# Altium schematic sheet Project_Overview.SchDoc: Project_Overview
size A4; Date: Not used; ApprovedBy: Not used; CheckedBy: Not used; Author: Not used; CompanyName: STMicroelectronics; DrawnBy: Not used; Engineer: Not used; Organization: Not used; Address1: Not used; Address2: Not used; Address3: Not used; Address4: Not used; DocumentNumber: 1; Revision: Not used; SheetNumber: 1; SheetTotal: 15
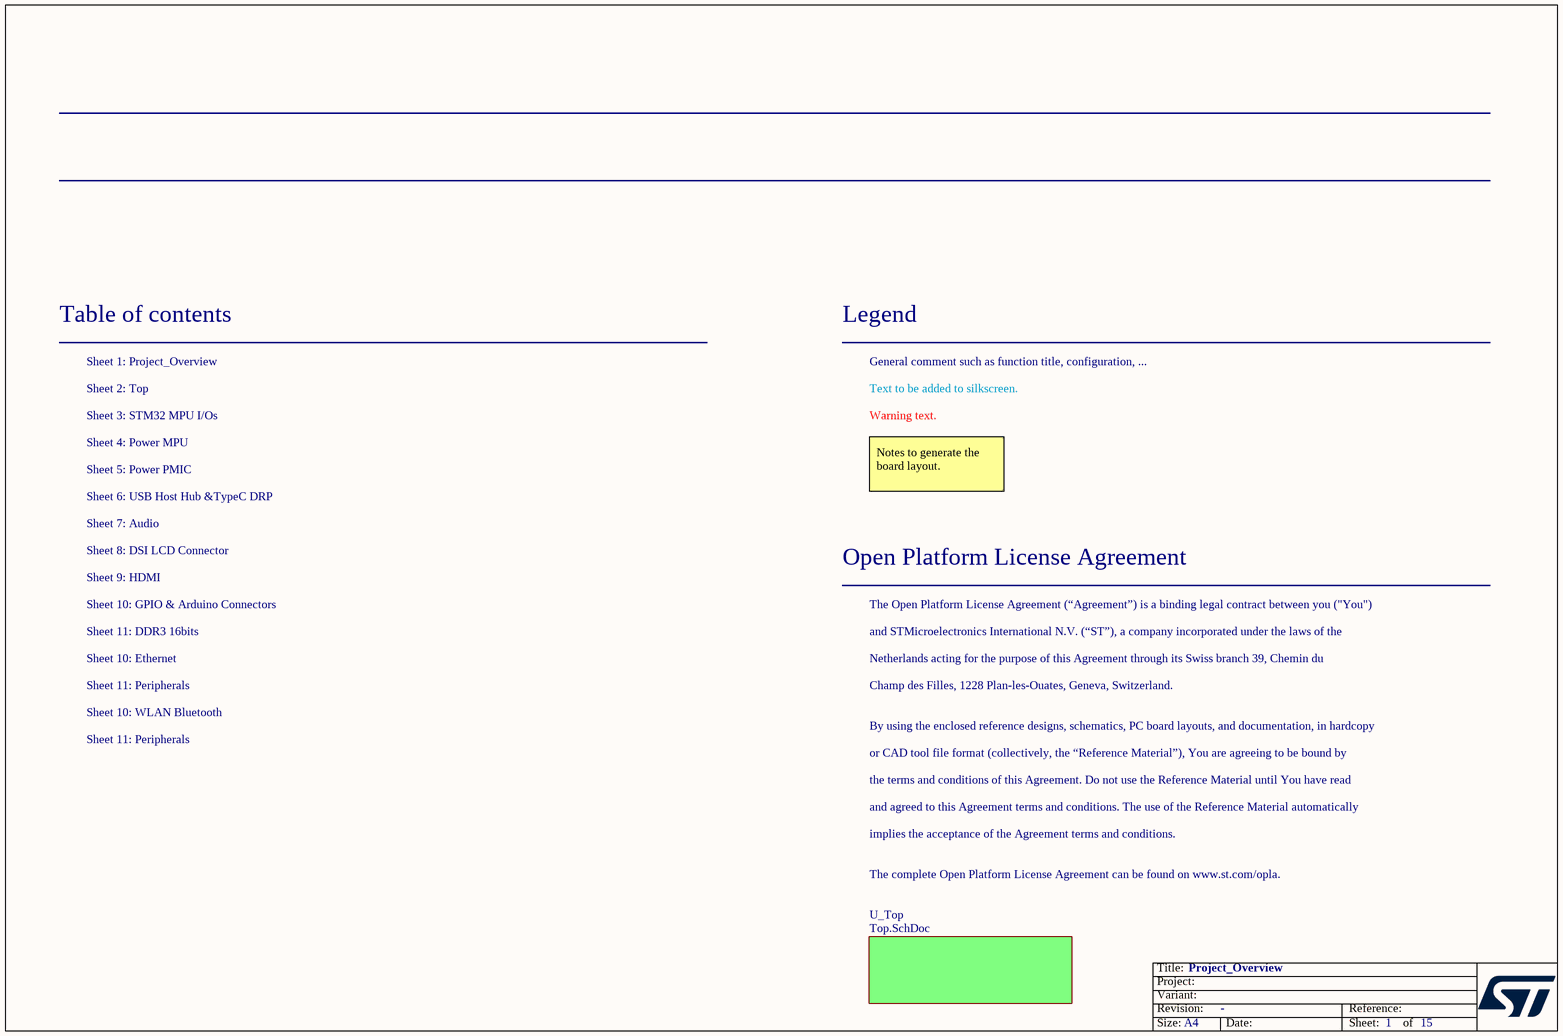
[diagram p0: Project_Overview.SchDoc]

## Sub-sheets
U_Top = Top.SchDoc: no entries

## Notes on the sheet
- Table of contents
- Sheet 1: Project_Overview
- Legend
- General comment such as function title, configuration, ...
- Sheet 2: Top
- Sheet 3: STM32 MPU I/Os
- Sheet 4: Power MPU
- Text to be added to silkscreen.
- Warning text.
- Sheet 6: USB Host Hub &TypeC DRP
- Sheet 5: Power PMIC
- Notes to generate the board layout.
- Sheet 7: Audio
- Sheet 9: HDMI
- Sheet 8: DSI LCD Connector
- Open Platform License Agreement
- Sheet 10: GPIO & Arduino Connectors
- Sheet 11: DDR3 16bits
- The Open Platform License Agreement (“Agreement”) is a binding legal contract between you ("You")
- and STMicroelectronics International N.V. (“ST”), a company incorporated under the laws of the
- Sheet 10: Ethernet
- Sheet 11: Peripherals
- Sheet 10: WLAN Bluetooth
- Netherlands acting for the purpose of this Agreement through its Swiss branch 39, Chemin du
- Champ des Filles, 1228 Plan-les-Ouates, Geneva, Switzerland.
- By using the enclosed reference designs, schematics, PC board layouts, and documentation, in hardcopy
- or CAD tool file format (collectively, the “Reference Material”), You are agreeing to be bound by
- the terms and conditions of this Agreement. Do not use the Reference Material until You have read
- and agreed to this Agreement terms and conditions. The use of the Reference Material automatically
- implies the acceptance of the Agreement terms and conditions.
- The complete Open Platform License Agreement can be found on www.st.com/opla.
